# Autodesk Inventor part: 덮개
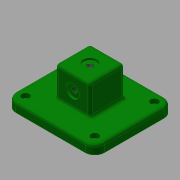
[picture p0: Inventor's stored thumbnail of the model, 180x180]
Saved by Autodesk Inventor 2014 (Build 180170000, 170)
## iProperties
Created: 2017-08
Part Number: 덮개
Material: 알루미늄 6061
Document SubType Name: Modeling
Designer: mduedu
Density: 1 g/cm^3
Appearance: 진녹색
Author: mduedu
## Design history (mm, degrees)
sketch "스케치1"
  geometry: L1 (46, -41)-(-46, -41); L2 (-46, -41)-(-46, 41); L3 (-46, 41)-(46, 41); L4 (46, 41)-(46, -41); 1 further point
  constraints: 8 end point, 2 parallel, 1 horizontal, 1 perpendicular
  dimensions: "d0" = 92 distance of L2.end L3.end; "d2" = 82 distance of L1.end L2.end; "d3" = 41 distance from line of L3 point (0, 0) (= 0.5 x d2); "d4" = 46 distance from line of point (0, 0) L4 (= 0.5 x d0)
extrude "돌출1" new body sketch "스케치1" distance "d5" = 10; taper "d6" = 0 deg
sketch "스케치2"
  geometry: L1 (-18, -18)-(18, -18); L2 (18, -18)-(18, 18); L3 (18, 18)-(-18, 18); L4 (-18, 18)-(-18, -18); L5 (-18, -18)-(18, 18); L6 (18, -18)-(-18, 18); 1 further point
  constraints: 12 end point, 2 midpoint, 2 parallel, 2 perpendicular, 1 horizontal
  dimensions: "d7" = 36 distance of L2.end L3.end
extrude "돌출2" join sketch "스케치2" distance "d9" = 32; taper "d10" = 0 deg
sketch "스케치3"
  geometry: L1 (-26, -26)-(26, -26); L2 (26, -26)-(26, 26); L3 (26, 26)-(-26, 26); L4 (-26, 26)-(-26, -26); L5 (-26, -26)-(26, 26); L6 (26, -26)-(-26, 26); 1 further point
  constraints: 12 end point, 2 midpoint, 2 parallel, 2 perpendicular, 1 horizontal
  dimensions: "d11" = 52 distance of L3.end L2.end
extrude "돌출3" join sketch "스케치3" distance "d12" = 6; taper "d13" = 0 deg
sketch "스케치4"
  geometry: L1 (-17, -17)-(17, -17); L2 (17, -17)-(17, 17); L3 (17, 17)-(-17, 17); L4 (-17, 17)-(-17, -17); L5 (-17, -17)-(17, 17); L6 (17, -17)-(-17, 17); 1 further point
  constraints: 12 end point, 2 midpoint, 2 parallel, 2 perpendicular, 1 horizontal
  dimensions: "d14" = 34 distance of L2.end L3.end
extrude "돌출4" cut sketch "스케치4" distance "d16" = 5; taper "d17" = 0 deg
sketch "스케치5"
  geometry: C1 r 9 at (0, 0); 1 further point
  constraints: 1 centre point, 1 coincident
  dimensions: "d18" = 18 diameter of C1
extrude "돌출5" cut sketch "스케치5" distance "d19" = 34; taper "d20" = 0 deg
sketch "스케치6"
  geometry: 2 further points
  constraints: 1 coincident
hole "구멍1" sketch "스케치6" at (0, 0) diameter "d21" = 5.917; stored, may be unused: countersink angle "d25" = 90 deg, drill point angle "d27" = 118 deg; dims "d22" = 6, "d23" = 14, "d24" = 2, "d26" = 8
sketch "스케치7"
  geometry: L1 (-28, -10)-(64, -10) reference; 3 further points
  constraints: 1 midpoint, 1 vertical alignment
  dimensions: "d47" = 26 distance from line of point (18, 16) L1
hole "구멍2" sketch "스케치7" at (18, 16) diameter "d29" = 5.917; stored, may be unused: countersink angle "d33" = 90 deg, drill point angle "d35" = 118 deg; dims "d30" = 6, "d31" = 14, "d32" = 2, "d34" = 8
fillet "모깎기1" dims "d36" = 10
fillet "모깎기2" dims "d37" = 3
fillet "모깎기3" dims "d38" = 3
fillet "모깎기4" dims "d39" = 3
fillet "모깎기5" dims "d40" = 3
chamfer "모따기1" distance "d41" = 1; stored, may be unused: second distance "d42" = 2, angle "d43" = 45 deg
fillet "모깎기6" dims "d44" = 3
fillet "모깎기7" dims "d45" = 3
fillet "모깎기8" dims "d46" = 3
sketch "스케치8"
  geometry: A1 r 10 centre (-36, -31) between (-46, -31) and (-36, -41) reference; A2 r 10 centre (-36, 31) between (-36, 41) and (-46, 31) reference; A3 r 10 centre (36, 31) between (46, 31) and (36, 41) reference; A4 r 10 centre (36, -31) between (36, -41) and (46, -31) reference; 5 further points
  constraints: 4 coincident
sketch "스케치9"
  geometry: 4 further points
  constraints: 4 other
hole "구멍3" sketch "스케치9" at (-36, -31), (-36, 31), (36, 31), (36, -31) diameter "d48" = 4.5; stored, may be unused: countersink angle "d52" = 90 deg, drill point angle "d54" = 0 deg; dims "d49" = 6, "d50" = 8, "d51" = 4.6, "d53" = 8
node "솔리드1"
